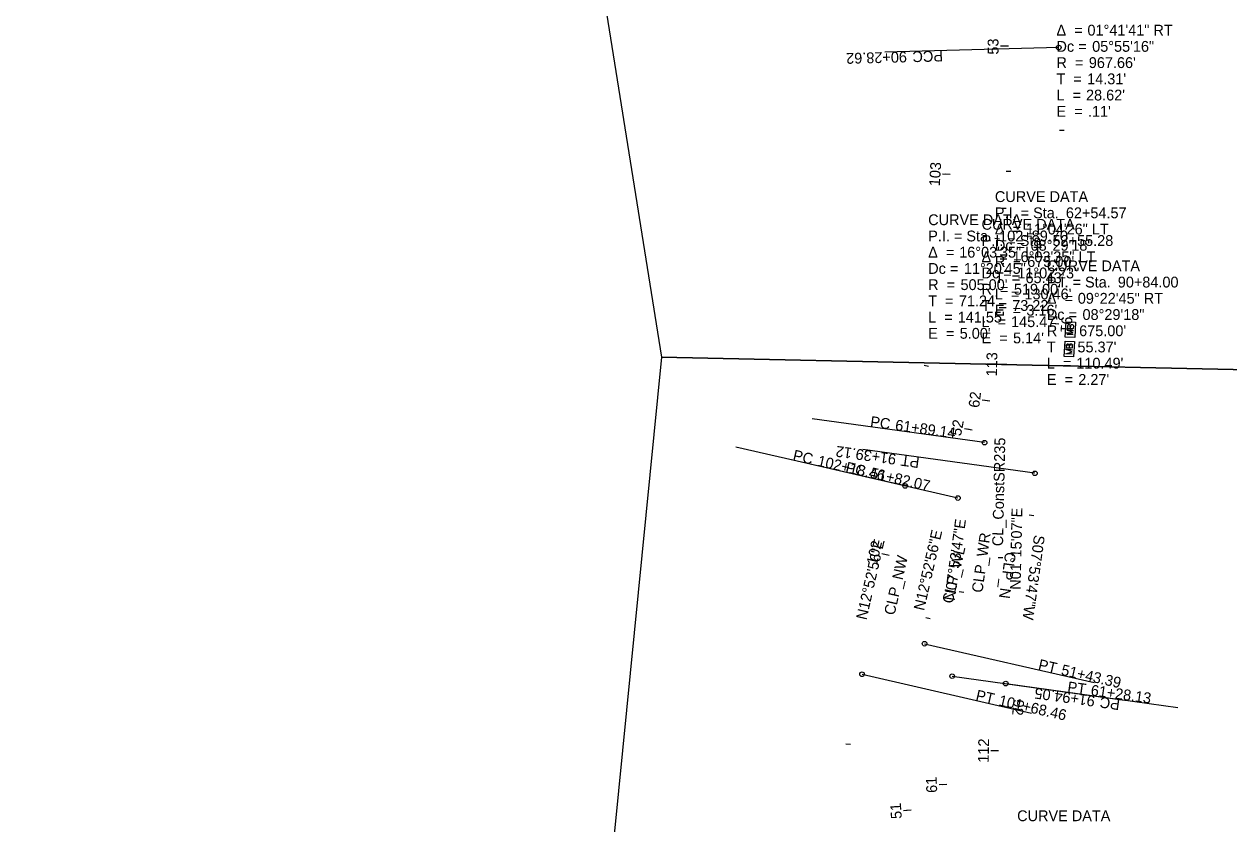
# Model space of a CAD drawing. Extents: x 1564517 to 1565226, y 635740 to 637455.
# Drawn here: x 1564517 to 1564828.9, y 636631.2 to 636838.2 of the extents above; entities that cross this region are included whole.
import ezdxf

# ---------------------------------------------------------------- set-up
doc = ezdxf.new("R2010")
doc.units = 0
for name, color, linetype in [('GE_P_Alignment_1000_Bearings', 7, 'Continuous'), ('GE_P_Alignment_1000_Distances', 7, 'Continuous'), ('GE_P_Alignment_500_Bearings', 7, 'Continuous'), ('GE_P_Alignment_500_Distances', 7, 'Continuous'), ('GK_Drainage_Nodes', 7, 'Continuous'), ('RD_P_Cells', 7, 'Continuous'), ('SC_Scratch10', 7, 'Continuous'), ('TX_P_1000', 7, 'Continuous'), ('UT_P_Water', 7, 'Continuous'), ('UT_P_Water_Cells', 7, 'Continuous'), ('UT_X_Electric', 7, 'Continuous'), ('UT_X_Sanitary_Pressure_Line', 7, 'Continuous'), ('UT_X_Water_Cells', 7, 'Continuous')]:
    doc.layers.add(name, color=color, linetype=linetype)

msp = doc.modelspace()

# ---------------------------------------------------------------- linework, layer by layer
at = {"layer": 'RD_P_Cells'}
for p, q in [((1564787.88, 636759.15), (1564787.88, 636759.15)), ((1564787.61, 636754.15), (1564787.61, 636754.15))]:
    msp.add_line(p, q, dxfattribs=at)
for points in [[(1564786.56, 636757.22), (1564786.77, 636761.22), (1564789.21, 636761.08), (1564789, 636757.09)], [(1564786.28, 636752.22), (1564786.5, 636756.22), (1564788.94, 636756.08), (1564788.72, 636752.09)]]:
    msp.add_lwpolyline(points, close=True, dxfattribs=at)
for points in [[(1564787.87, 636760.18), (1564787.81, 636760.24), (1564787.78, 636760.28), (1564787.74, 636760.31), (1564787.71, 636760.32), (1564787.67, 636760.35), (1564787.63, 636760.37), (1564787.54, 636760.4), (1564787.5, 636760.4), (1564787.45, 636760.4), (1564787.38, 636760.39), (1564787.31, 636760.37), (1564787.26, 636760.34), (1564787.21, 636760.28), (1564787.18, 636760.23), (1564787.17, 636760.2), (1564787.14, 636760.14), (1564787.1, 636759.52), (1564788.7, 636759.44), (1564788.74, 636760.13), (1564788.69, 636760.22), (1564788.63, 636760.3), (1564788.54, 636760.37), (1564788.43, 636760.41), (1564788.31, 636760.43), (1564788.24, 636760.43), (1564788.16, 636760.41), (1564788.05, 636760.37), (1564787.97, 636760.31), (1564787.87, 636760.18), (1564787.83, 636759.48)], [(1564788.61, 636757.81), (1564787.02, 636757.9), (1564788.64, 636758.39), (1564787.08, 636759.03), (1564788.67, 636758.95)], [(1564788.34, 636752.81), (1564786.74, 636752.9), (1564788.37, 636753.39), (1564786.8, 636754.03), (1564788.4, 636753.95)], [(1564787.6, 636755.18), (1564787.54, 636755.24), (1564787.5, 636755.28), (1564787.47, 636755.31), (1564787.44, 636755.32), (1564787.39, 636755.35), (1564787.35, 636755.37), (1564787.27, 636755.4), (1564787.23, 636755.4), (1564787.18, 636755.4), (1564787.1, 636755.39), (1564787.04, 636755.37), (1564786.99, 636755.34), (1564786.93, 636755.28), (1564786.91, 636755.23), (1564786.89, 636755.2), (1564786.86, 636755.14), (1564786.83, 636754.52), (1564788.43, 636754.44), (1564788.46, 636755.13), (1564788.42, 636755.22), (1564788.36, 636755.3), (1564788.26, 636755.37), (1564788.15, 636755.41), (1564788.04, 636755.43), (1564787.96, 636755.43), (1564787.89, 636755.41), (1564787.77, 636755.37), (1564787.69, 636755.31), (1564787.6, 636755.18), (1564787.56, 636754.48)]]:
    msp.add_lwpolyline(points, dxfattribs=at)
at = {"layer": 'TX_P_1000'}
for p, q in [((1564765.66, 636729.91), (1564721.08, 636736.1)), ((1564758.76, 636715.58), (1564714.89, 636725.62)), ((1564750.13, 636677.88), (1564794, 636667.84)), ((1564757.28, 636669.48), (1564801.85, 636663.3))]:
    msp.add_line(p, q, dxfattribs=at)
at = {"layer": 'UT_P_Water_Cells'}
for p, q in [((1564784.86, 636832.17), (1564739.88, 636831)), ((1564771.82, 636832.54), (1564770.62, 636832.53)), ((1564756.8, 636799.31), (1564755.61, 636799.39)), ((1564782.94, 636760.85), (1564784.13, 636760.75)), ((1564771.47, 636750.1), (1564770.27, 636750.13)), ((1564767.06, 636740.68), (1564765.87, 636740.83)), ((1564765.66, 636729.91), (1564721.08, 636736.1)), ((1564762.45, 636733.13), (1564761.27, 636733.36)), ((1564745.11, 636718.7), (1564701.24, 636728.74)), ((1564778.69, 636721.97), (1564734.12, 636728.15)), ((1564758.76, 636715.58), (1564714.89, 636725.62)), ((1564740.99, 636700.71), (1564739.82, 636700.98)), ((1564750.13, 636677.88), (1564794, 636667.84)), ((1564733.96, 636669.96), (1564777.83, 636659.93)), ((1564757.28, 636669.48), (1564801.85, 636663.3)), ((1564771.14, 636667.56), (1564815.72, 636661.38)), ((1564770.45, 636661.65), (1564771.64, 636661.53)), ((1564769.29, 636650.12), (1564768.09, 636650.15)), ((1564755.87, 636641.43), (1564754.68, 636641.38)), ((1564746.67, 636634.78), (1564745.47, 636634.7))]:
    msp.add_line(p, q, dxfattribs=at)
for centre in [(1564784.86, 636832.17), (1564765.66, 636729.91), (1564778.69, 636721.97), (1564745.11, 636718.7), (1564758.76, 636715.58), (1564750.13, 636677.88), (1564733.96, 636669.96), (1564757.28, 636669.48), (1564771.14, 636667.56)]:
    msp.add_circle(centre, 0.6, dxfattribs=at)
at = {"layer": 'UT_X_Electric'}
for points in [[(1564682.06, 636752.05), (1564842.01, 636748.56), (1564861.83, 636755.87), (1564842.73, 637279.63), (1564517.04, 637293.63), (1564662.12, 636876.82)], [(1564685.49, 636222.38), (1564930.72, 636197.15), (1564955.53, 636388.56), (1565013.42, 636482), (1565045.03, 636594.7), (1564968.04, 636598.47), (1565001.39, 636689.39), (1564864.83, 636740.08), (1564842.01, 636748.56), (1564682.06, 636752.05), (1564649.71, 636425.72), (1564708.41, 636418.15)]]:
    msp.add_lwpolyline(points, close=True, dxfattribs=at)
at = {"layer": 'UT_X_Sanitary_Pressure_Line'}
for p, q in [((1564765.66, 636729.91), (1564721.08, 636736.1)), ((1564745.11, 636718.7), (1564701.24, 636728.74)), ((1564778.69, 636721.97), (1564734.12, 636728.15)), ((1564758.76, 636715.58), (1564714.89, 636725.62)), ((1564750.13, 636677.88), (1564794, 636667.84)), ((1564733.96, 636669.96), (1564777.83, 636659.93)), ((1564757.28, 636669.48), (1564801.85, 636663.3)), ((1564771.14, 636667.56), (1564815.72, 636661.38))]:
    msp.add_line(p, q, dxfattribs=at)
for centre in [(1564765.66, 636729.91), (1564778.69, 636721.97), (1564745.11, 636718.7), (1564758.76, 636715.58), (1564750.13, 636677.88), (1564733.96, 636669.96), (1564757.28, 636669.48), (1564771.14, 636667.56)]:
    msp.add_circle(centre, 0.6, dxfattribs=at)
at = {"layer": 'UT_X_Water_Cells'}
for p, q in [((1564771.82, 636832.54), (1564769.82, 636832.53)), ((1564785.08, 636810.79), (1564786.28, 636810.79)), ((1564772.46, 636800.09), (1564771.26, 636800.1)), ((1564756.8, 636799.31), (1564754.81, 636799.44)), ((1564771.29, 636790.49), (1564770.09, 636790.55)), ((1564769.53, 636782.61), (1564768.34, 636782.72)), ((1564782.94, 636760.85), (1564784.93, 636760.69)), ((1564771.47, 636750.1), (1564769.47, 636750.14)), ((1564751.17, 636749.65), (1564749.99, 636749.84)), ((1564767.06, 636740.68), (1564765.08, 636740.93)), ((1564762.45, 636733.13), (1564760.49, 636733.51)), ((1564777.2, 636711.19), (1564778.38, 636711.03)), ((1564740.99, 636700.71), (1564739.04, 636701.15)), ((1564770.38, 636700.11), (1564769.18, 636700.14)), ((1564760.28, 636691.15), (1564759.09, 636691.31)), ((1564751.61, 636684.32), (1564750.44, 636684.59)), ((1564770.45, 636661.65), (1564772.44, 636661.46)), ((1564730.96, 636651.76), (1564729.77, 636651.88)), ((1564769.29, 636650.12), (1564767.29, 636650.17)), ((1564755.87, 636641.43), (1564753.88, 636641.35)), ((1564746.67, 636634.78), (1564744.67, 636634.65))]:
    msp.add_line(p, q, dxfattribs=at)
for centre in [(1564750.13, 636677.88), (1564757.28, 636669.48)]:
    msp.add_circle(centre, 0.6, dxfattribs=at)

# ---------------------------------------------------------------- texts
at = {"layer": 'GE_P_Alignment_1000_Bearings'}
msp.add_text('N01°15\'07"E', height=2.8, rotation=88.748, dxfattribs=at).set_placement((1564775, 636691.81))
at = {"layer": 'GE_P_Alignment_1000_Distances'}
msp.add_text('CL_ConstSR235', height=2.8, rotation=88.748, dxfattribs=at).set_placement((1564770.44, 636703.09))
at = {"layer": 'GE_P_Alignment_500_Bearings'}
msp.add_text('N01°15\'07"E', height=2.8, rotation=88.748, dxfattribs=at).set_placement((1564775, 636691.81))
at = {"layer": 'GE_P_Alignment_500_Distances'}
msp.add_text('CL_ConstSR235', height=2.8, rotation=88.748, dxfattribs=at).set_placement((1564770.44, 636703.09))
at = {"layer": 'GK_Drainage_Nodes'}
for s, p in [('Δ  = ', (1564784.28, 636835.27)), ('01°41\'41" RT', (1564792.3, 636835.27)), ('Dc = ', (1564784.28, 636831.07)), ('05°55\'16"', (1564793.52, 636831.07)), ('R  = ', (1564784.28, 636826.87)), ("967.66'", (1564792.65, 636826.87)), ('T  = ', (1564784.28, 636822.67)), ("14.31'", (1564792.22, 636822.67)), ('L  = ', (1564784.28, 636818.47)), ("28.62'", (1564791.93, 636818.47)), ('E  = ', (1564784.28, 636814.27)), (".11'", (1564792.43, 636814.27)), ('CURVE DATA', (1564768.34, 636792.19)), ('P.I. = Sta. ', (1564768.34, 636787.99)), ('62+54.57', (1564786.71, 636787.99)), ('CURVE DATA', (1564751.07, 636786.2)), ('CURVE DATA', (1564764.89, 636785.02)), ('P.I. = Sta. ', (1564751.07, 636782)), ('Δ  = ', (1564768.34, 636783.79)), ('102+89.70', (1564769.44, 636782)), ('11°04\'26" LT', (1564776.36, 636783.79)), ('P.I. = Sta. ', (1564764.89, 636780.82)), ('Dc = ', (1564768.34, 636779.59)), ('08°29\'18"', (1564777.58, 636779.59)), ('52+55.28', (1564783.26, 636780.82)), ('Δ  = ', (1564751.07, 636777.8)), ('16°03\'35" LT', (1564759.1, 636777.8)), ('Δ  = ', (1564764.89, 636776.62)), ('R  = ', (1564768.34, 636775.39)), ('16°03\'35" LT', (1564772.91, 636776.62)), ("675.00'", (1564776.71, 636775.39)), ('Dc = ', (1564751.07, 636773.6)), ('11°20\'45"', (1564760.31, 636773.6)), ('Dc = ', (1564764.89, 636772.42)), ('11°02\'23"', (1564774.13, 636772.42)), ('CURVE DATA', (1564781.78, 636774.27)), ('R  = ', (1564751.07, 636769.4)), ("505.00'", (1564759.44, 636769.4)), ('T  = ', (1564768.34, 636771.19)), ("65.43'", (1564776.27, 636771.19)), ('P.I. = Sta. ', (1564781.78, 636770.07)), ('90+84.00', (1564800.15, 636770.07)), ('R  = ', (1564764.89, 636768.22)), ('L  = ', (1564768.34, 636766.99)), ("519.00'", (1564773.26, 636768.22)), ("130.46'", (1564775.99, 636766.99)), ('09°22\'45" RT', (1564789.8, 636765.87)), ('T  = ', (1564751.07, 636765.2)), ("71.24'", (1564759.01, 636765.2)), ('T  = ', (1564764.89, 636764.02)), ('E  = ', (1564768.34, 636762.79)), ("73.22'", (1564772.82, 636764.02)), ("3.16'", (1564776.49, 636762.79)), ('Δ  = ', (1564781.78, 636765.87)), ('L  = ', (1564751.07, 636761)), ("141.55'", (1564758.72, 636761)), ('L  = ', (1564764.89, 636759.82)), ("145.47'", (1564772.53, 636759.82)), ('Dc = ', (1564781.78, 636761.67)), ('08°29\'18"', (1564791.02, 636761.67)), ('E  = ', (1564751.07, 636756.8)), ("5.00'", (1564759.23, 636756.8)), ('R  = ', (1564781.78, 636757.47)), ("675.00'", (1564790.15, 636757.47)), ('E  = ', (1564764.89, 636755.62)), ("5.14'", (1564773.04, 636755.62)), ('T  = ', (1564781.78, 636753.27)), ("55.37'", (1564789.71, 636753.27)), ('L  = ', (1564781.78, 636749.07)), ("110.49'", (1564789.42, 636749.07)), ('E  = ', (1564781.78, 636744.87)), ("2.27'", (1564789.93, 636744.87)), ('CURVE DATA', (1564774.1, 636631.94))]:
    msp.add_text(s, height=2.8, dxfattribs=at).set_placement(p)
for s, rotation, p in [('N07°53\'47"E', 82.1036, (1564757.95, 636688.9)), ('N12°52\'56"E', 77.1178, (1564750, 636686.28)), ('CLP_WR', 82.1036, (1564765.1, 636690.95)), ('N12°52\'56"E', 77.1178, (1564735.09, 636683.88)), ('S07°53\'47"W', 262.1036, (1564778.51, 636706.13)), ('CLP_NW', 77.1178, (1564742.34, 636685.09)), ('CLP_WL', 77.1178, (1564757.39, 636688.09)), ('CLP_N', 262.1036, (1564771.04, 636701.73))]:
    msp.add_text(s, height=2.8, rotation=rotation, dxfattribs=at).set_placement(p)
at = {"layer": 'SC_Scratch10'}
for s, p in [('Δ  = ', (1564784.28, 636835.27)), ('01°41\'41" RT', (1564792.3, 636835.27)), ('Dc = ', (1564784.28, 636831.07)), ('05°55\'16"', (1564793.52, 636831.07)), ('R  = ', (1564784.28, 636826.87)), ("967.66'", (1564792.65, 636826.87)), ('T  = ', (1564784.28, 636822.67)), ("14.31'", (1564792.22, 636822.67)), ('L  = ', (1564784.28, 636818.47)), ("28.62'", (1564791.93, 636818.47)), ('E  = ', (1564784.28, 636814.27)), (".11'", (1564792.43, 636814.27)), ('CURVE DATA', (1564768.34, 636792.19)), ('P.I. = Sta. ', (1564768.34, 636787.99)), ('62+54.57', (1564786.71, 636787.99)), ('CURVE DATA', (1564751.07, 636786.2)), ('CURVE DATA', (1564764.89, 636785.02)), ('P.I. = Sta. ', (1564751.07, 636782)), ('Δ  = ', (1564768.34, 636783.79)), ('102+89.70', (1564769.44, 636782)), ('11°04\'26" LT', (1564776.36, 636783.79)), ('P.I. = Sta. ', (1564764.89, 636780.82)), ('Dc = ', (1564768.34, 636779.59)), ('08°29\'18"', (1564777.58, 636779.59)), ('52+55.28', (1564783.26, 636780.82)), ('Δ  = ', (1564751.07, 636777.8)), ('16°03\'35" LT', (1564759.1, 636777.8)), ('Δ  = ', (1564764.89, 636776.62)), ('R  = ', (1564768.34, 636775.39)), ('16°03\'35" LT', (1564772.91, 636776.62)), ("675.00'", (1564776.71, 636775.39)), ('Dc = ', (1564751.07, 636773.6)), ('11°20\'45"', (1564760.31, 636773.6)), ('Dc = ', (1564764.89, 636772.42)), ('11°02\'23"', (1564774.13, 636772.42)), ('CURVE DATA', (1564781.78, 636774.27)), ('R  = ', (1564751.07, 636769.4)), ("505.00'", (1564759.44, 636769.4)), ('T  = ', (1564768.34, 636771.19)), ("65.43'", (1564776.27, 636771.19)), ('P.I. = Sta. ', (1564781.78, 636770.07)), ('90+84.00', (1564800.15, 636770.07)), ('R  = ', (1564764.89, 636768.22)), ('L  = ', (1564768.34, 636766.99)), ("519.00'", (1564773.26, 636768.22)), ("130.46'", (1564775.99, 636766.99)), ('09°22\'45" RT', (1564789.8, 636765.87)), ('T  = ', (1564751.07, 636765.2)), ("71.24'", (1564759.01, 636765.2)), ('T  = ', (1564764.89, 636764.02)), ('E  = ', (1564768.34, 636762.79)), ("73.22'", (1564772.82, 636764.02)), ("3.16'", (1564776.49, 636762.79)), ('Δ  = ', (1564781.78, 636765.87)), ('L  = ', (1564751.07, 636761)), ("141.55'", (1564758.72, 636761)), ('L  = ', (1564764.89, 636759.82)), ("145.47'", (1564772.53, 636759.82)), ('Dc = ', (1564781.78, 636761.67)), ('08°29\'18"', (1564791.02, 636761.67)), ('E  = ', (1564751.07, 636756.8)), ("5.00'", (1564759.23, 636756.8)), ('R  = ', (1564781.78, 636757.47)), ("675.00'", (1564790.15, 636757.47)), ('E  = ', (1564764.89, 636755.62)), ("5.14'", (1564773.04, 636755.62)), ('T  = ', (1564781.78, 636753.27)), ("55.37'", (1564789.71, 636753.27)), ('L  = ', (1564781.78, 636749.07)), ("110.49'", (1564789.42, 636749.07)), ('E  = ', (1564781.78, 636744.87)), ("2.27'", (1564789.93, 636744.87)), ('CURVE DATA', (1564774.1, 636631.94))]:
    msp.add_text(s, height=2.8, dxfattribs=at).set_placement(p)
for s, rotation, p in [('N07°53\'47"E', 82.1036, (1564757.95, 636688.9)), ('N12°52\'56"E', 77.1178, (1564750, 636686.28)), ('CLP_WR', 82.1036, (1564765.1, 636690.95)), ('N12°52\'56"E', 77.1178, (1564735.09, 636683.88)), ('S07°53\'47"W', 262.1036, (1564778.51, 636706.13)), ('CLP_NW', 77.1178, (1564742.34, 636685.09)), ('CLP_WL', 77.1178, (1564757.39, 636688.09)), ('CLP_N', 262.1036, (1564771.04, 636701.73))]:
    msp.add_text(s, height=2.8, rotation=rotation, dxfattribs=at).set_placement(p)
at = {"layer": 'UT_P_Water'}
for s, p in [('Δ  = ', (1564784.28, 636835.27)), ('01°41\'41" RT', (1564792.3, 636835.27)), ('Dc = ', (1564784.28, 636831.07)), ('05°55\'16"', (1564793.52, 636831.07)), ('R  = ', (1564784.28, 636826.87)), ("967.66'", (1564792.65, 636826.87)), ('T  = ', (1564784.28, 636822.67)), ("14.31'", (1564792.22, 636822.67)), ('L  = ', (1564784.28, 636818.47)), ("28.62'", (1564791.93, 636818.47)), ('E  = ', (1564784.28, 636814.27)), (".11'", (1564792.43, 636814.27)), ('CURVE DATA', (1564768.34, 636792.19)), ('P.I. = Sta. ', (1564768.34, 636787.99)), ('62+54.57', (1564786.71, 636787.99)), ('CURVE DATA', (1564751.07, 636786.2)), ('CURVE DATA', (1564764.89, 636785.02)), ('P.I. = Sta. ', (1564751.07, 636782)), ('Δ  = ', (1564768.34, 636783.79)), ('102+89.70', (1564769.44, 636782)), ('11°04\'26" LT', (1564776.36, 636783.79)), ('P.I. = Sta. ', (1564764.89, 636780.82)), ('Dc = ', (1564768.34, 636779.59)), ('08°29\'18"', (1564777.58, 636779.59)), ('52+55.28', (1564783.26, 636780.82)), ('Δ  = ', (1564751.07, 636777.8)), ('16°03\'35" LT', (1564759.1, 636777.8)), ('Δ  = ', (1564764.89, 636776.62)), ('R  = ', (1564768.34, 636775.39)), ('16°03\'35" LT', (1564772.91, 636776.62)), ("675.00'", (1564776.71, 636775.39)), ('Dc = ', (1564751.07, 636773.6)), ('11°20\'45"', (1564760.31, 636773.6)), ('Dc = ', (1564764.89, 636772.42)), ('11°02\'23"', (1564774.13, 636772.42)), ('CURVE DATA', (1564781.78, 636774.27)), ('R  = ', (1564751.07, 636769.4)), ("505.00'", (1564759.44, 636769.4)), ('T  = ', (1564768.34, 636771.19)), ("65.43'", (1564776.27, 636771.19)), ('P.I. = Sta. ', (1564781.78, 636770.07)), ('90+84.00', (1564800.15, 636770.07)), ('R  = ', (1564764.89, 636768.22)), ('L  = ', (1564768.34, 636766.99)), ("519.00'", (1564773.26, 636768.22)), ("130.46'", (1564775.99, 636766.99)), ('09°22\'45" RT', (1564789.8, 636765.87)), ('T  = ', (1564751.07, 636765.2)), ("71.24'", (1564759.01, 636765.2)), ('T  = ', (1564764.89, 636764.02)), ('E  = ', (1564768.34, 636762.79)), ("73.22'", (1564772.82, 636764.02)), ("3.16'", (1564776.49, 636762.79)), ('Δ  = ', (1564781.78, 636765.87)), ('L  = ', (1564751.07, 636761)), ("141.55'", (1564758.72, 636761)), ('L  = ', (1564764.89, 636759.82)), ("145.47'", (1564772.53, 636759.82)), ('Dc = ', (1564781.78, 636761.67)), ('08°29\'18"', (1564791.02, 636761.67)), ('E  = ', (1564751.07, 636756.8)), ("5.00'", (1564759.23, 636756.8)), ('R  = ', (1564781.78, 636757.47)), ("675.00'", (1564790.15, 636757.47)), ('E  = ', (1564764.89, 636755.62)), ("5.14'", (1564773.04, 636755.62)), ('T  = ', (1564781.78, 636753.27)), ("55.37'", (1564789.71, 636753.27)), ('L  = ', (1564781.78, 636749.07)), ("110.49'", (1564789.42, 636749.07)), ('E  = ', (1564781.78, 636744.87)), ("2.27'", (1564789.93, 636744.87)), ('CURVE DATA', (1564774.1, 636631.94))]:
    msp.add_text(s, height=2.8, dxfattribs=at).set_placement(p)
for s, rotation, p in [('N07°53\'47"E', 82.1036, (1564757.95, 636688.9)), ('N12°52\'56"E', 77.1178, (1564750, 636686.28)), ('CLP_WR', 82.1036, (1564765.1, 636690.95)), ('N12°52\'56"E', 77.1178, (1564735.09, 636683.88)), ('S07°53\'47"W', 262.1036, (1564778.51, 636706.13)), ('CLP_NW', 77.1178, (1564742.34, 636685.09)), ('CLP_WL', 77.1178, (1564757.39, 636688.09)), ('CLP_N', 262.1036, (1564771.04, 636701.73))]:
    msp.add_text(s, height=2.8, rotation=rotation, dxfattribs=at).set_placement(p)
at = {"layer": 'UT_P_Water_Cells'}
for s, rotation, p in [('90+28.62', 181.4827, (1564745.53, 636831.15)), ('PCC', 181.4827, (1564754.87, 636831.39)), ('PC', 352.1036, (1564735.94, 636734.03)), ('61+89.14', 352.1036, (1564742.4, 636733.14)), ('91+39.12', 172.1036, (1564742.95, 636726.93)), ('PC', 347.1178, (1564715.86, 636725.39)), ('102+18.46', 347.1178, (1564722.22, 636723.94)), ('PT', 172.1036, (1564748.97, 636726.09)), ('PC', 347.1178, (1564729.51, 636722.27)), ('51+82.07', 347.1178, (1564735.87, 636720.82)), ('PT', 347.1178, (1564779.38, 636671.19)), ('51+43.39', 347.1178, (1564785.31, 636669.83)), ('PT', 347.1178, (1564763.21, 636663.27)), ('91+94.05', 172.1036, (1564794.4, 636664.33)), ('PT', 352.1036, (1564786.99, 636665.36)), ('61+28.13', 352.1036, (1564793.02, 636664.52)), ('101+68.46', 347.1178, (1564769.14, 636661.92)), ('PC', 172.1036, (1564800.86, 636663.44))]:
    msp.add_text(s, height=2.8, rotation=rotation, dxfattribs=at).set_placement(p)
at = {"layer": 'UT_X_Sanitary_Pressure_Line'}
for s, rotation, p in [('PC', 352.1036, (1564735.94, 636734.03)), ('61+89.14', 352.1036, (1564742.4, 636733.14)), ('91+39.12', 172.1036, (1564742.95, 636726.93)), ('PC', 347.1178, (1564715.86, 636725.39)), ('102+18.46', 347.1178, (1564722.22, 636723.94)), ('PT', 172.1036, (1564748.97, 636726.09)), ('PC', 347.1178, (1564729.51, 636722.27)), ('51+82.07', 347.1178, (1564735.87, 636720.82)), ('PT', 347.1178, (1564779.38, 636671.19)), ('51+43.39', 347.1178, (1564785.31, 636669.83)), ('PT', 347.1178, (1564763.21, 636663.27)), ('91+94.05', 172.1036, (1564794.4, 636664.33)), ('PT', 352.1036, (1564786.99, 636665.36)), ('61+28.13', 352.1036, (1564793.02, 636664.52)), ('101+68.46', 347.1178, (1564769.14, 636661.92)), ('PC', 172.1036, (1564800.86, 636663.44))]:
    msp.add_text(s, height=2.8, rotation=rotation, dxfattribs=at).set_placement(p)
at = {"layer": 'UT_X_Water_Cells'}
for s, rotation, p in [('53', 90.1372, (1564769.28, 636830.35)), ('103', 86.3689, (1564754.06, 636796.21)), ('91', 265.4241, (1564785.64, 636762.66)), ('113', 88.748, (1564768.86, 636747.04)), ('62', 83.0256, (1564764.27, 636738.82)), ('52', 79.0976, (1564759.54, 636731.47)), ('102', 77.1178, (1564737.78, 636698.08)), ('92', 264.4393, (1564773.19, 636663.58)), ('112', 88.748, (1564766.72, 636647.05)), ('61', 92.1763, (1564753.41, 636639.31)), ('51', 93.6904, (1564744.26, 636632.59))]:
    msp.add_text(s, height=2.8, rotation=rotation, dxfattribs=at).set_placement(p)

doc.saveas('drawing.dxf')
